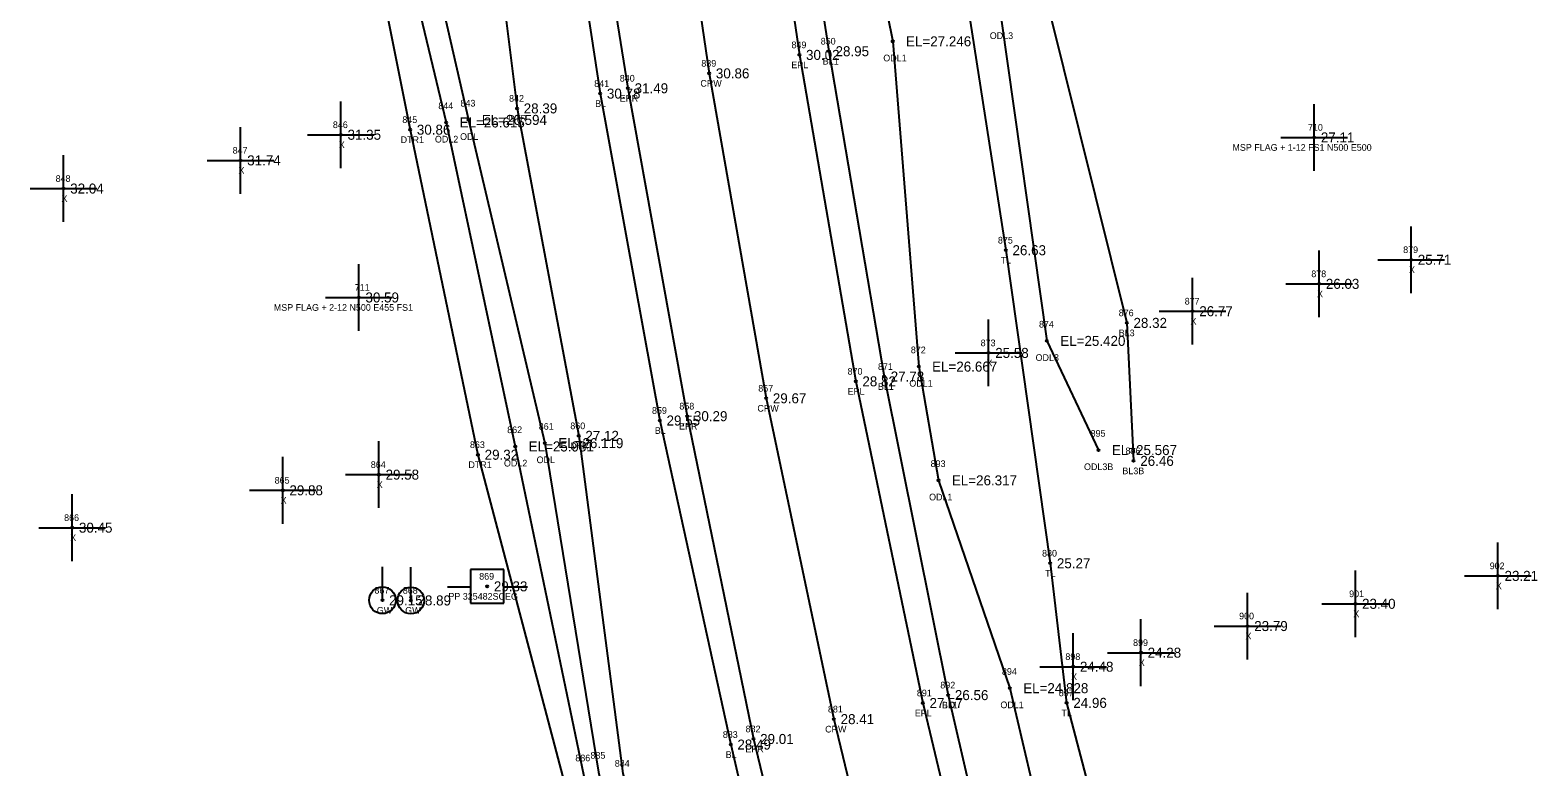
# Model space of a CAD drawing. Extents: x 2042211 to 2045853, y 303080 to 309569.
# Drawn here: x 2042763.3 to 2042989.1, y 306930.4 to 307040.8 of the extents above; entities that cross this region are included whole.
import ezdxf

# ---------------------------------------------------------------- set-up
doc = ezdxf.new("R2010")
doc.units = 0
for name, color, linetype in [('BR_500YR_SCOUR', 7, 'Continuous'), ('RD_DTM_BkLn1', 7, 'Continuous'), ('RD_DTM_BkLn_txCode', 7, 'Continuous'), ('RD_EX_H2O', 7, 'Continuous'), ('RD_EX_H2O_txCode', 7, 'Continuous'), ('RD_EX_Misc', 7, 'Continuous'), ('RD_EX_Misc_txCode', 7, 'Continuous'), ('RD_EX_Road', 7, 'Continuous'), ('RD_EX_Road_txCode', 7, 'Continuous'), ('RD_EX_TX_H2O_ELEV', 7, 'Continuous'), ('RD_EX_TX_Misc_ELEV', 7, 'Continuous'), ('RD_EX_TX_Road_ELEV', 7, 'Continuous'), ('RD_EX_TX_UT_ELEV', 7, 'Continuous'), ('RD_EX_TX_VEG_ELEV', 7, 'Continuous'), ('RD_EX_UT_txCode', 7, 'Continuous'), ('RD_EX_VEG_txCode', 7, 'Continuous'), ('RD_HC_Survey_ELEV', 7, 'Continuous'), ('RD_HC_Survey_txCode', 7, 'Continuous'), ('RD_SMD_Locator', 7, 'Continuous')]:
    doc.layers.add(name, color=color, linetype=linetype)

msp = doc.modelspace()

# ---------------------------------------------------------------- linework, layer by layer
at = {"layer": 'BR_500YR_SCOUR'}
for p, q in [((2042816.09, 306955.4), (2042816.09, 306960.4)), ((2042820.34, 306955.38), (2042820.34, 306960.38)), ((2042834.28, 306959.99), (2042829.28, 306959.99)), ((2042829.28, 306959.99), (2042829.28, 306954.99)), ((2042834.28, 306954.99), (2042834.28, 306959.99)), ((2042825.84, 306957.43), (2042829.31, 306957.43)), ((2042834.2, 306957.43), (2042837.84, 306957.43)), ((2042829.28, 306954.99), (2042834.28, 306954.99))]:
    msp.add_line(p, q, dxfattribs=at)
msp.add_lwpolyline([(2042880.44, 307351.7), (2042880.19, 307284.9), (2042884.99, 307224.08), (2042886.48, 307195.22), (2042890.83, 307127.55), (2042909.45, 307007.86), (2042916.1, 306960.95), (2042918.56, 306940.03), (2042926.66, 306909), (2042942.91, 306849.91), (2042954.33, 306802.72), (2042963.56, 306806.84), (2042974.33, 306847.25), (2043002.07, 306860.54), (2043032.14, 306846.51)], dxfattribs=at)
for centre, radius in [((2042909.45, 307007.86), 0.15), ((2042916.1, 306960.95), 0.15), ((2042816.09, 306955.4), 2), ((2042820.34, 306955.38), 2), ((2042831.78, 306957.49), 0.15), ((2042816.09, 306955.4), 0.15), ((2042820.34, 306955.38), 0.15), ((2042918.56, 306940.03), 0.15)]:
    msp.add_circle(centre, radius, dxfattribs=at)
at = {"layer": 'RD_DTM_BkLn1'}
for points in [[(2042839.81, 307329.37), (2042840.93, 307280.46), (2042843.39, 307231.17), (2042846.87, 307181.66), (2042851.76, 307132.07), (2042857.83, 307083.36), (2042865.03, 307034.36), (2042873.56, 306985.67), (2042883.71, 306937.59), (2042895.32, 306889.27), (2042908.01, 306841.41), (2042921.81, 306793.88), (2042936.83, 306746.34), (2042953.05, 306699.55), (2042970.36, 306653.6), (2042989.25, 306607.34), (2043009.36, 306561.99), (2043030.44, 306517.39), (2043052.89, 306472.91), (2043076.3, 306429.26), (2043100.43, 306386.21)], [(2042857.66, 307329.64), (2042861.09, 307281.84), (2042862.27, 307232.19), (2042866.29, 307183.84), (2042870.56, 307134.28), (2042875.48, 307086.26), (2042882.95, 307037.68), (2042891.21, 306988.93), (2042900.82, 306941.19), (2042911.81, 306893.75), (2042924.4, 306846), (2042938.51, 306799.29), (2042953.5, 306752.33), (2042968.09, 306705.62), (2042985.63, 306659.36), (2043004.49, 306613.62), (2043024.61, 306569.26), (2043045.97, 306525.25), (2043068.43, 306480.84), (2043092.42, 306438.64), (2043116.55, 306395.12)], [(2042904.11, 307124.26), (2042907.26, 307092.26), (2042915.67, 307044.76), (2042927.57, 306996.97), (2042928.59, 306976.29)], [(2042839.17, 307095.11), (2042841.19, 307080.52), (2042848.71, 307031.33), (2042857.64, 306982.34), (2042868.25, 306933.78), (2042879.62, 306884.9), (2042891.37, 306836.61), (2042906.05, 306788.56), (2042920.38, 306740.36), (2042936.3, 306692.68), (2042942.2, 306670.77), (2042952.72, 306646.49), (2042972.88, 306600.44), (2042993.94, 306554.96), (2043015.19, 306509.48), (2043037.06, 306464.5), (2043060.22, 306420.45)]]:
    msp.add_lwpolyline(points, dxfattribs=at)
at = {"layer": 'RD_EX_H2O'}
for points in [[(2042866.82, 307329.93), (2042876.23, 307282.16), (2042878.43, 307232.86), (2042875.08, 307184.77), (2042887.19, 307136.65), (2042884.32, 307120.02), (2042882.74, 307087.49), (2042892.51, 307039.16), (2042896.41, 306990.42), (2042899.37, 306973.37), (2042910.05, 306942.23), (2042920.75, 306896.67), (2042927.15, 306846.78), (2042945.6, 306801.59), (2042960.32, 306754.61), (2042976.65, 306708.74), (2042994.63, 306662.76), (2043013.3, 306616.98), (2043029.17, 306571.91), (2043050.77, 306528.53)], [(2042809.74, 307126.16), (2042806.56, 307122.63), (2042790.31, 307116.78), (2042788.49, 307114.78), (2042791.89, 307113.57), (2042804.81, 307114.94), (2042810.25, 307075.93), (2042820.25, 307025.92), (2042830.4, 306977.21), (2042843.29, 306928.12), (2042852.91, 306878.24), (2042864.55, 306828.43), (2042879.23, 306781.72), (2042889.45, 306748.73), (2042886.16, 306741.98), (2042888.34, 306727.94), (2042896.13, 306676.35), (2042885.67, 306665.43), (2042857.25, 306612.72)], [(2042809.74, 307126.16), (2042815.01, 307124.31), (2042821.79, 307118.99), (2042825.8, 307110.2), (2042827.88, 307100.21), (2042830.08, 307078.71), (2042836.25, 307029.11), (2042845.48, 306980.04), (2042852.07, 306929.46), (2042864.58, 306881.26), (2042879.31, 306833.06), (2042893.37, 306784.78), (2042908.76, 306736.23), (2042928.77, 306689.39), (2042938.94, 306669.11)], [(2042896.98, 307122.86), (2042898.29, 307090.91), (2042908.74, 307042.51), (2042915.6, 306994.27), (2042923.33, 306977.91)], [(2042812.2, 307117.75), (2042817.66, 307076.99), (2042828.97, 307027.39), (2042840.42, 306978.95), (2042848.44, 306929.66), (2042859.84, 306880.36), (2042873.68, 306831.67), (2042888.54, 306783.43), (2042900.59, 306749.27), (2042902.9, 306733.67), (2042926.04, 306688.21), (2042936.45, 306668.37), (2042947.44, 306643.99), (2042966.18, 306597.91), (2042985.34, 306551.14), (2042987.61, 306538.59)], [(2042810.02, 307117.36), (2042813.87, 307076.18), (2042825.65, 307027), (2042835.99, 306978.45), (2042846.19, 306929.27), (2042857.5, 306879.97), (2042870.3, 306830.67), (2042885.37, 306782.68), (2042895.57, 306748.28), (2042892.03, 306740.63), (2042891.66, 306731.27), (2042905.95, 306680.58), (2042906.87, 306643.18), (2042864.97, 306605.63)]]:
    msp.add_lwpolyline(points, dxfattribs=at)
at = {"layer": 'RD_EX_Misc'}
for p, q in [((2042809.87, 307020.16), (2042809.87, 307030.16)), ((2042955.63, 307019.76), (2042955.63, 307029.76)), ((2042794.84, 307016.32), (2042794.84, 307026.32)), ((2042804.87, 307025.16), (2042814.87, 307025.16)), ((2042950.63, 307024.76), (2042960.63, 307024.76)), ((2042768.33, 307012.1), (2042768.33, 307022.1)), ((2042789.84, 307021.32), (2042799.84, 307021.32)), ((2042763.33, 307017.1), (2042773.33, 307017.1)), ((2042970.14, 307001.43), (2042970.14, 307011.43)), ((2042956.38, 306997.82), (2042956.38, 307007.82)), ((2042812.55, 306995.78), (2042812.55, 307005.78)), ((2042965.14, 307006.43), (2042975.14, 307006.43)), ((2042937.42, 306993.72), (2042937.42, 307003.72)), ((2042951.38, 307002.82), (2042961.38, 307002.82)), ((2042807.55, 307000.78), (2042817.55, 307000.78)), ((2042932.42, 306998.72), (2042942.42, 306998.72)), ((2042906.86, 306987.47), (2042906.86, 306997.47)), ((2042901.86, 306992.47), (2042911.86, 306992.47)), ((2042815.56, 306969.23), (2042815.56, 306979.23)), ((2042801.16, 306966.88), (2042801.16, 306976.88)), ((2042810.56, 306974.23), (2042820.56, 306974.23)), ((2042769.64, 306961.28), (2042769.64, 306971.28)), ((2042796.16, 306971.88), (2042806.16, 306971.88)), ((2042764.64, 306966.28), (2042774.64, 306966.28)), ((2042983.14, 306954.06), (2042983.14, 306964.06)), ((2042961.8, 306949.87), (2042961.8, 306959.87)), ((2042978.14, 306959.06), (2042988.14, 306959.06)), ((2042945.65, 306946.54), (2042945.65, 306956.54)), ((2042956.8, 306954.87), (2042966.8, 306954.87)), ((2042919.55, 306940.45), (2042919.55, 306950.45)), ((2042929.69, 306942.55), (2042929.69, 306952.55)), ((2042940.65, 306951.54), (2042950.65, 306951.54)), ((2042924.69, 306947.55), (2042934.69, 306947.55)), ((2042914.55, 306945.45), (2042924.55, 306945.45))]:
    msp.add_line(p, q, dxfattribs=at)
at = {"layer": 'RD_EX_Road'}
for points in [[(2042826.88, 307329.29), (2042828.01, 307279.82), (2042830.5, 307230.24), (2042834.09, 307180.37), (2042835.89, 307157.73), (2042833.55, 307154.38), (2042836.54, 307132.83), (2042837.33, 307130.11), (2042837.64, 307128.77), (2042839.22, 307126.16), (2042844.98, 307081.33), (2042852.86, 307032.13), (2042861.74, 306982.99), (2042871.66, 306934.62), (2042883.38, 306885.88), (2042895.94, 306837.56), (2042909.76, 306789.89)], [(2042853.31, 307329.44), (2042854.43, 307281.38), (2042857.15, 307232.07), (2042860.27, 307183.35), (2042865.16, 307133.89), (2042871.37, 307085.7), (2042878.53, 307037.13), (2042886.97, 306988.21), (2042897.02, 306940.01), (2042908.28, 306892.66), (2042921.09, 306844.85), (2042934.41, 306798.2), (2042949.37, 306750.96), (2042965.62, 306704.44), (2042983.48, 306658.43), (2043001.91, 306612.18), (2043021.64, 306567.98), (2043042.58, 306523.81), (2043065.05, 306479.23), (2043088.14, 306436.09), (2043112.53, 306392.81)]]:
    msp.add_lwpolyline(points, dxfattribs=at)
at = {"layer": 'RD_SMD_Locator'}
for centre in [(2042892.51, 307039.16), (2042878.53, 307037.13), (2042882.95, 307037.68), (2042865.03, 307034.36), (2042852.86, 307032.13), (2042848.71, 307031.33), (2042825.65, 307027), (2042828.97, 307027.39), (2042836.25, 307029.11), (2042809.87, 307025.16), (2042820.25, 307025.92), (2042955.63, 307024.76), (2042794.84, 307021.32), (2042768.33, 307017.1), (2042970.14, 307006.43), (2042956.38, 307002.82), (2042812.55, 307000.78), (2042937.42, 306998.72), (2042927.57, 306996.97), (2042915.6, 306994.27), (2042906.86, 306992.47), (2042891.21, 306988.93), (2042896.41, 306990.42), (2042886.97, 306988.21), (2042873.56, 306985.67), (2042857.64, 306982.34), (2042861.74, 306982.99), (2042845.48, 306980.04), (2042835.99, 306978.45), (2042840.42, 306978.95), (2042923.33, 306977.91), (2042830.4, 306977.21), (2042928.59, 306976.29), (2042815.56, 306974.23), (2042899.37, 306973.37), (2042801.16, 306971.88), (2042769.64, 306966.28), (2042983.14, 306959.06), (2042961.8, 306954.87), (2042945.65, 306951.54), (2042929.69, 306947.55), (2042919.55, 306945.45), (2042900.82, 306941.19), (2042910.05, 306942.23), (2042897.02, 306940.01), (2042883.71, 306937.59), (2042871.66, 306934.62), (2042868.25, 306933.78)]:
    msp.add_circle(centre, 0.15, dxfattribs=at)

# ---------------------------------------------------------------- texts
at = {"layer": 'RD_DTM_BkLn_txCode'}
for s, p in [('850', (2042881.73, 307038.68)), ('BL1', (2042882.03, 307035.68)), ('841', (2042847.81, 307032.33)), ('BL', (2042847.95, 307029.33)), ('876', (2042926.36, 306997.97)), ('BL3', (2042926.36, 306994.97)), ('871', (2042890.31, 306989.93)), ('BL1', (2042890.29, 306986.93)), ('859', (2042856.46, 306983.34)), ('BL', (2042856.88, 306980.34)), ('896', (2042927.38, 306977.29)), ('BL3B', (2042926.91, 306974.29)), ('892', (2042899.64, 306942.19)), ('BL1', (2042899.9, 306939.19)), ('883', (2042867.07, 306934.78)), ('BL', (2042867.5, 306931.78))]:
    msp.add_text(s, height=1, dxfattribs=at).set_placement(p)
at = {"layer": 'RD_EX_H2O_txCode'}
for s, p in [('ODL3', (2042907.05, 307039.51)), ('ODL1', (2042891.1, 307036.16)), ('844', (2042824.46, 307029)), ('843', (2042827.78, 307029.39)), ('842', (2042835.06, 307030.11)), ('845', (2042819.07, 307026.92)), ('DTR', (2042834.98, 307027.11)), ('DTR1', (2042818.82, 307023.92)), ('ODL2', (2042823.95, 307024)), ('ODL', (2042827.72, 307024.39)), ('874', (2042914.42, 306996.27)), ('872', (2042895.23, 306992.42)), ('ODL3', (2042913.91, 306991.27)), ('ODL1', (2042895, 306987.42)), ('860', (2042844.23, 306981.04)), ('862', (2042834.78, 306980.45)), ('861', (2042839.5, 306980.95)), ('895', (2042922.15, 306979.91)), ('863', (2042829.2, 306978.21)), ('DTR', (2042844.21, 306978.04)), ('DTR1', (2042828.97, 306975.21)), ('ODL2', (2042834.29, 306975.45)), ('ODL', (2042839.18, 306975.95)), ('893', (2042898.19, 306975.37)), ('ODL3B', (2042921.16, 306974.91)), ('ODL1', (2042897.96, 306970.37)), ('894', (2042908.87, 306944.23)), ('ODL1', (2042908.64, 306939.23)), ('885', (2042847.25, 306931.66)), ('886', (2042844.98, 306931.27)), ('884', (2042850.89, 306930.46))]:
    msp.add_text(s, height=1, dxfattribs=at).set_placement(p)
at = {"layer": 'RD_EX_Misc_txCode'}
for s, p in [('846', (2042808.67, 307026.16)), ('710', (2042954.7, 307025.76)), ('847', (2042793.66, 307022.32)), ('X', (2042809.56, 307023.16)), ('MSP FLAG + 1-12 FS1 N500 E500', (2042943.39, 307022.76)), ('848', (2042767.15, 307018.1)), ('X', (2042794.53, 307019.32)), ('X', (2042768.02, 307015.1)), ('879', (2042968.96, 307007.43)), ('878', (2042955.2, 307003.82)), ('X', (2042969.83, 307004.43)), ('711', (2042811.94, 307001.78)), ('877', (2042936.24, 306999.72)), ('X', (2042956.06, 307000.82)), ('MSP FLAG + 2-12 N500 E455 FS1', (2042799.82, 306998.78)), ('X', (2042937.1, 306996.72)), ('873', (2042905.68, 306993.47)), ('X', (2042906.55, 306990.47)), ('864', (2042814.35, 306975.23)), ('865', (2042799.95, 306972.88)), ('X', (2042815.24, 306972.23)), ('X', (2042800.84, 306969.88)), ('866', (2042768.42, 306967.28)), ('X', (2042769.33, 306964.28)), ('902', (2042981.92, 306960.06)), ('X', (2042982.83, 306957.06)), ('901', (2042960.87, 306955.87)), ('900', (2042944.39, 306952.54)), ('X', (2042961.49, 306952.87)), ('X', (2042945.34, 306949.54)), ('899', (2042928.51, 306948.55)), ('898', (2042918.37, 306946.45)), ('X', (2042929.37, 306945.55)), ('X', (2042919.23, 306943.45))]:
    msp.add_text(s, height=1, dxfattribs=at).set_placement(p)
at = {"layer": 'RD_EX_Road_txCode'}
for s, p in [('849', (2042877.35, 307038.13)), ('840', (2042851.64, 307033.13)), ('EPL', (2042877.32, 307035.13)), ('EPR', (2042851.63, 307030.13)), ('870', (2042885.75, 306989.21)), ('EPL', (2042885.76, 306986.21)), ('858', (2042860.56, 306983.99)), ('EPR', (2042860.51, 306980.99)), ('891', (2042896.13, 306941.01)), ('EPL', (2042895.82, 306938.01)), ('882', (2042870.48, 306935.62)), ('EPR', (2042870.44, 306932.62))]:
    msp.add_text(s, height=1, dxfattribs=at).set_placement(p)
at = {"layer": 'RD_EX_TX_H2O_ELEV'}
for s, p in [('EL=27.246', (2042894.51, 307038.41)), ('28.39', (2042837.25, 307028.36)), ('EL=26.615', (2042827.65, 307026.25)), ('EL=26.594', (2042830.97, 307026.64)), ('30.86', (2042821.25, 307025.17)), ('EL=25.420', (2042917.6, 306993.52)), ('EL=26.667', (2042898.41, 306989.67)), ('EL=26.119', (2042842.42, 306978.2)), ('27.12', (2042846.48, 306979.29)), ('29.32', (2042831.4, 306976.46)), ('EL=25.931', (2042837.99, 306977.7)), ('EL=25.567', (2042925.33, 306977.16)), ('EL=26.317', (2042901.37, 306972.62)), ('EL=24.828', (2042912.05, 306941.48))]:
    msp.add_text(s, height=1.5, dxfattribs=at).set_placement(p)
at = {"layer": 'RD_EX_TX_Misc_ELEV'}
for s, p in [('28.95', (2042883.95, 307036.93)), ('30.78', (2042849.71, 307030.58)), ('31.35', (2042810.87, 307024.41)), ('27.11', (2042956.63, 307024.01)), ('31.74', (2042795.84, 307020.57)), ('32.04', (2042769.33, 307016.35)), ('25.71', (2042971.14, 307005.68)), ('26.03', (2042957.38, 307002.07)), ('30.59', (2042813.55, 307000.03)), ('26.77', (2042938.42, 306997.97)), ('28.32', (2042928.57, 306996.22)), ('25.58', (2042907.86, 306991.72)), ('27.78', (2042892.21, 306988.18)), ('29.55', (2042858.64, 306981.59)), ('26.46', (2042929.59, 306975.54)), ('29.58', (2042816.56, 306973.48)), ('29.88', (2042802.16, 306971.13)), ('30.45', (2042770.64, 306965.53)), ('23.21', (2042984.14, 306958.31)), ('23.40', (2042962.8, 306954.12)), ('23.79', (2042946.65, 306950.79)), ('24.28', (2042930.69, 306946.8)), ('24.48', (2042920.55, 306944.7)), ('26.56', (2042901.82, 306940.44)), ('28.49', (2042869.25, 306933.03))]:
    msp.add_text(s, height=1.5, dxfattribs=at).set_placement(p)
at = {"layer": 'RD_EX_TX_Road_ELEV'}
for s, p in [('30.02', (2042879.53, 307036.38)), ('31.49', (2042853.86, 307031.38)), ('28.82', (2042887.97, 306987.46)), ('30.29', (2042862.74, 306982.24)), ('27.57', (2042898.02, 306939.26)), ('29.01', (2042872.66, 306933.87))]:
    msp.add_text(s, height=1.5, dxfattribs=at).set_placement(p)
at = {"layer": 'RD_EX_TX_UT_ELEV'}
for s, p in [('29.15', (2042817.09, 306954.65)), ('28.89', (2042821.34, 306954.63))]:
    msp.add_text(s, height=1.5, dxfattribs=at).set_placement(p)
at = {"layer": 'RD_EX_TX_VEG_ELEV'}
for s, p in [('26.63', (2042910.45, 307007.11)), ('25.27', (2042917.1, 306960.2)), ('24.96', (2042919.56, 306939.28))]:
    msp.add_text(s, height=1.5, dxfattribs=at).set_placement(p)
at = {"layer": 'RD_EX_UT_txCode'}
for s, p in [('869', (2042830.58, 306958.49)), ('867', (2042814.89, 306956.4)), ('868', (2042819.14, 306956.38)), ('PP 325482SCEG', (2042825.97, 306955.49)), ('GW', (2042815.25, 306953.4)), ('GW', (2042819.5, 306953.38))]:
    msp.add_text(s, height=1, dxfattribs=at).set_placement(p)
at = {"layer": 'RD_EX_VEG_txCode'}
for s, p in [('875', (2042908.27, 307008.86)), ('TL', (2042908.68, 307005.86)), ('880', (2042914.88, 306961.95)), ('TL', (2042915.33, 306958.95)), ('897', (2042917.38, 306941.03)), ('TL', (2042917.79, 306938.03))]:
    msp.add_text(s, height=1, dxfattribs=at).set_placement(p)
at = {"layer": 'RD_HC_Survey_ELEV'}
for s, p in [('30.86', (2042866.03, 307033.61)), ('29.67', (2042874.56, 306984.92)), ('29.33', (2042832.78, 306956.74)), ('28.41', (2042884.71, 306936.84))]:
    msp.add_text(s, height=1.5, dxfattribs=at).set_placement(p)
at = {"layer": 'RD_HC_Survey_txCode'}
for s, p in [('839', (2042863.85, 307035.36)), ('CRW', (2042863.71, 307032.36)), ('857', (2042872.38, 306986.67)), ('CRW', (2042872.25, 306983.67)), ('881', (2042882.81, 306938.59)), ('CRW', (2042882.39, 306935.59))]:
    msp.add_text(s, height=1, dxfattribs=at).set_placement(p)

doc.saveas('drawing.dxf')
